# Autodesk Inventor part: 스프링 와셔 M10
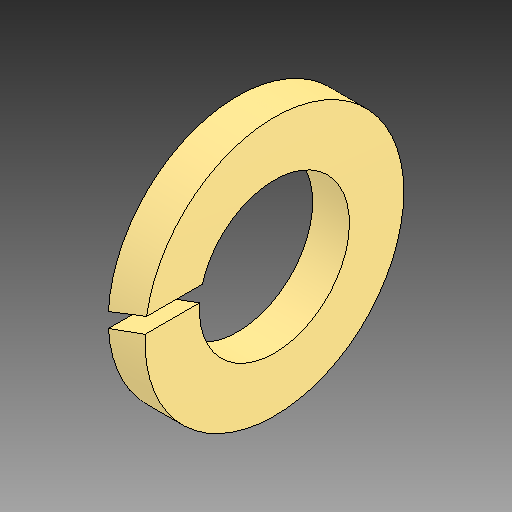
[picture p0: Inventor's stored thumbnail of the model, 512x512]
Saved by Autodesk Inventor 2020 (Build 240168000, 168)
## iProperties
Created: 2024-08
Part Number: 스프링 와셔 M10
Material: 강철, 연강
Description: 스프링 잠금 와셔
Document SubType Name: Modeling
Designer: 1강의실14
Density: 7.85 g/cm^3
Appearance: 기본값
Author: jhkim
Sending System: Autodesk Inventor 2025
Preprocessor: ST-DEVELOPER v20
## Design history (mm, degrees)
feature "Solid1"
node "솔리드1"
